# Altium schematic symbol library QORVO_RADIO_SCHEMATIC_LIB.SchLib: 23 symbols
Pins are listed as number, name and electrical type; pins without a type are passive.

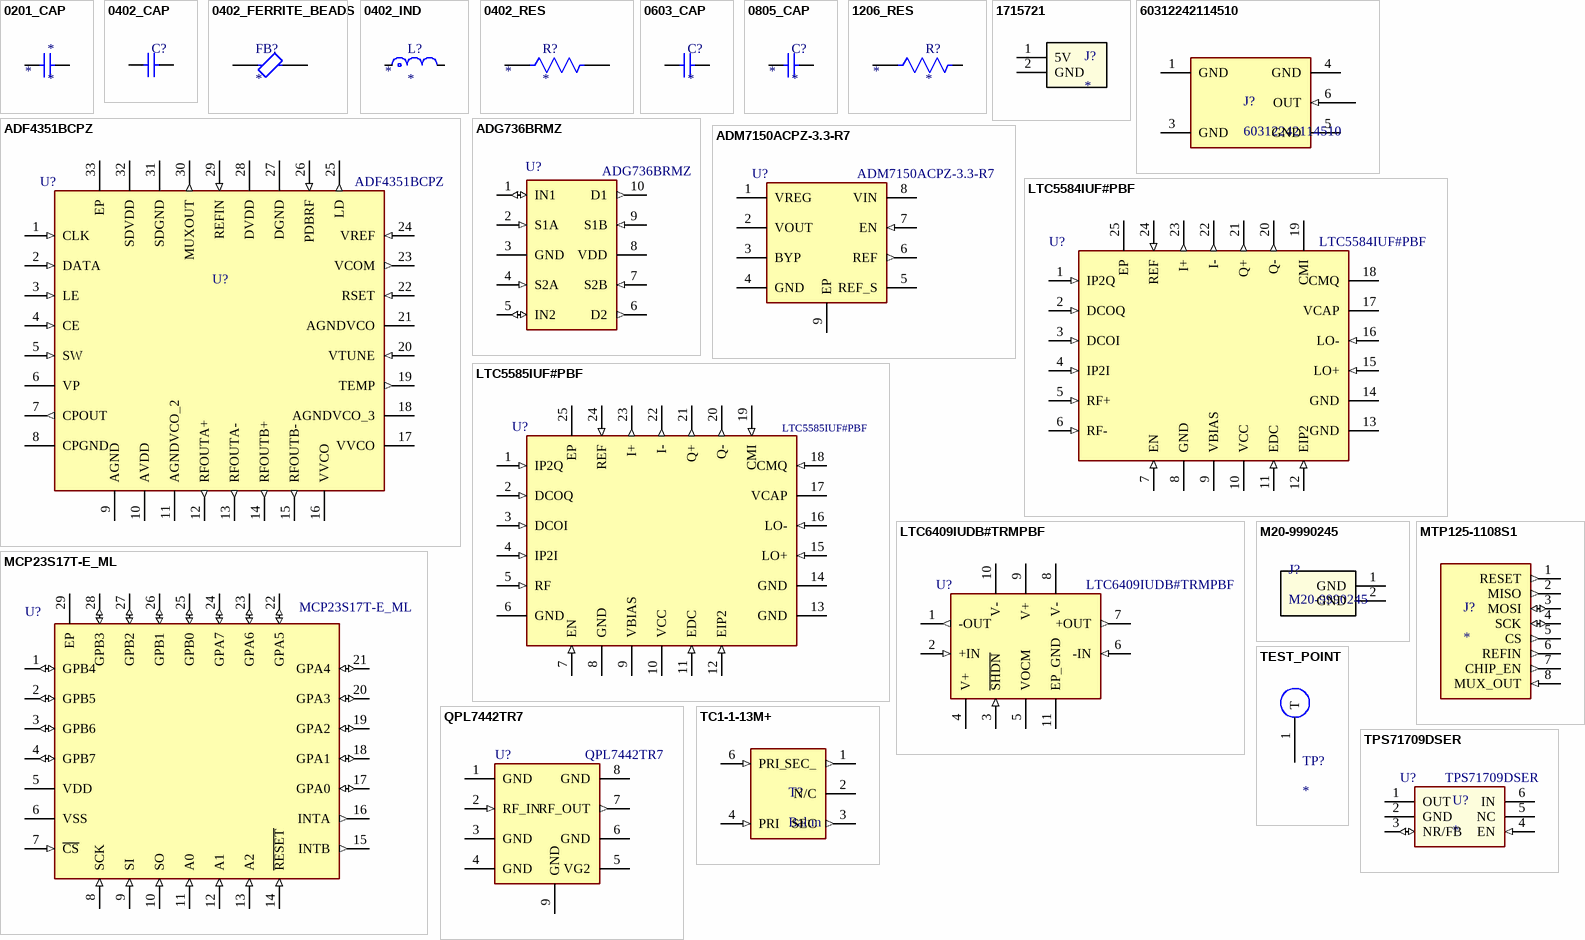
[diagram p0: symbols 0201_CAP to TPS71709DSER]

## 0201_CAP
designator *
CAPACITOR
footprint 0201_CAP
pins: 1, 2

## 0402_CAP
designator C?
CAPACITOR
footprint 0402 CAP_IND_RES
pins: 1, 2

## 0402_FERRITE_BEADS
designator FB?
FERRITE BEADS
footprint 0402 CAP_IND_RES
pins: 1, 2

## 0402_IND
designator L?
INDUCTOR
footprint 0402 CAP_IND_RES
pins: 1, 2

## 0402_RES
designator R?
RESISTOR
footprint 0402 CAP_IND_RES
pins: 1, 2

## 0603_CAP
designator C?
CAPACITOR
footprint 0603_CAP
pins: 1, 2

## 0805_CAP
designator C?
CAPACITOR
footprint 0805_CAP
pins: 1, 2

## 1206_RES
designator R?
RESISTOR
footprint 1206_RES
pins: 1, 2

## 1715721
designator J?
1x2P 17.5A 250V Green 14~30 Direct Insert 5.08mm 1 2 Plugin,P=5.08mm Screw Terminal Blocks ROHS; Mfr_Name: Phoenix Contact
footprint 1715721 (PS CONNECTOR)
pins: 1 5V (power), 2 GND (power)

## 60312242114510
designator J?
1 SMA Board Edge 18GHz 50Ω -  RF Connectors / Coaxial Connectors ROHS
footprint 60312242114510 (FEMALE SMA - EDGE MOUNT)
pins: 1 GND (power), 3 GND (power), 4 GND (power), 5 GND (power), 6 OUT (in)

## ADF4351BCPZ
designator U?  (value not drawn)
4.4GHz LFCSP-32(5x5) Clock Generators, PLLs, Frequency Synthesizers ROHS; Manufacturer_Name: Analog Devices; Manufacturer_Part_Number: ADF4351BCPZ
footprint ADF4351BCPZ (WIDEBAND SYNTHESIZER)
pins: 1 CLK (in), 2 DATA (in), 3 LE (in), 4 CE (in), 5 SW (in), 6 VP (power), 7 CPOUT (out), 8 CPGND (power), 9 AGND (power), 10 AVDD (power), 11 AGNDVCO_2 (power), 12 RFOUTA+ (out), 13 RFOUTA- (out), 14 RFOUTB+ (out), 15 RFOUTB- (out), 16 VVCO (power), 17 VVCO (power), 18 AGNDVCO_3 (power), 19 TEMP (out), 20 VTUNE (in), 21 AGNDVCO (power), 22 RSET (in), 23 VCOM (out), 24 VREF (in), 25 LD (out), 26 PDBRF (in), 27 DGND (power), 28 DVDD (power), 29 REFIN (in), 30 MUXOUT (out), 31 SDGND (power), 32 SDVDD (power), 33 EP (power)

## ADG736BRMZ
designator U?
2 4Ω SPDT(SPDT) MSOP-10  Analog Switches, Multiplexers ROHS; Manufacturer_Name: Analog Devices
footprint ADG736BRMZ
pins: 1 IN1 (io), 2 S1A (in), 3 GND (power), 4 S2A (in), 5 IN2 (io), 6 D2 (out), 7 S2B (in), 8 VDD (power), 9 S1B (in), 10 D1 (out)

## ADM7150ACPZ-3.3-R7
designator U?
800mA 68dB@(1MHz) Fixed 3.3V Positive electrode 16V LFCSP-8-EP(3x3) Voltage Regulators - Linear, Low Drop Out (LDO) Regulators ROHS; Manufacturer_Name: Analog Devices
footprint ADM7150ACPZ-3.3-R7 (3.3V REG)
pins: 1 VREG (power), 2 VOUT (power), 3 BYP, 4 GND (power), 5 REF_S, 6 REF (out), 7 EN (in), 8 VIN (power), 9 EP (power)

## LTC5584IUF#PBF
designator U?
30MHz~1.4GHz 9.9dB 5.4dB QFN-24-EP(4x4) RF Modulators and Demodulators ROHS; Manufacturer_Name: Analog Devices
footprint LTC5584/LTC5585 (MIXERS / LTC5585IUF#PBF / LTC5584IUF#PBF)
pins: 1 IP2Q (in), 2 DCOQ (in), 3 DCOI (in), 4 IP2I (in), 5 RF+ (in), 6 RF- (in), 7 EN (in), 8 GND (power), 9 VBIAS (power), 10 VCC (power), 11 EDC (in), 12 EIP2 (in), 13 GND (power), 14 GND (power), 15 LO+ (in), 16 LO- (in), 17 VCAP (power), 18 CMQ (power), 19 CMI (power), 20 Q- (out), 21 Q+ (out), 22 I- (out), 23 I+ (out), 24 REF (in), 25 EP (power)

## LTC5585IUF#PBF
designator U?
400MHz~4GHz 12.7dB 2.4dB QFN-24-EP(4x4)  RF Modulators and Demodulators ROHS; Manufacturer_Name: Analog Devices
footprint LTC5584/LTC5585 (MIXERS / LTC5585IUF#PBF / LTC5584IUF#PBF)
pins: 1 IP2Q (in), 2 DCOQ (in), 3 DCOI (in), 4 IP2I (in), 5 RF (in), 6 GND (power), 7 EN (in), 8 GND (power), 9 VBIAS (power), 10 VCC (power), 11 EDC (in), 12 EIP2 (in), 13 GND (power), 14 GND (power), 15 LO+ (in), 16 LO- (in), 17 VCAP (power), 18 CMQ (in), 19 CMI (in), 20 Q- (out), 21 Q+ (out), 22 I- (out), 23 I+ (out), 24 REF (in), 25 EP (power)

## LTC6409IUDB#TRMPBF
designator U?
QFN-10(2x3)  Differential Amplifiers ROHS; Manufacturer_Name: Analog Devices
footprint LTC6409IUDB#TRMPBF (DIFFERENTAL OP-AMP)
pins: 1 -OUT (out), 2 +IN (in), 3 ~{SHDN} (in), 4 V+ (power), 5 VOCM (power), 6 -IN (in), 7 +OUT (out), 8 V- (power), 9 V+ (power), 10 V- (power), 11 EP_GND (power)

## M20-9990245
designator J?
2 PIN HEADER FOR GND; Mfr_Name: Harwin
footprint GND_TEST (TEST POINT FOR GND HEADER)
pins: 1 GND (power), 2 GND (power)

## MCP23S17T-E_ML
designator U?
10MHz SPI QFN-28-EP(6x6) I/O Expanders ROHS; Manufacturer_Name: Microchip; Manufacturer_Part_Number: MCP23S17T-E/ML
footprint MCP23S17T-E_ML (I/O EXPANDER)
pins: 1 GPB4 (io), 2 GPB5 (io), 3 GPB6 (io), 4 GPB7 (io), 5 VDD (power), 6 VSS (power), 7 ~{CS} (in), 8 SCK (in), 9 SI (in), 10 SO (in), 11 A0 (in), 12 A1 (in), 13 A2 (in), 14 ~{RESET} (in), 15 INTB (out), 16 INTA (out), 17 GPA0 (io), 18 GPA1 (io), 19 GPA2 (io), 20 GPA3 (io), 21 GPA4 (io), 22 GPA5 (io), 23 GPA6 (io), 24 GPA7 (io), 25 GPB0 (io), 26 GPB1 (io), 27 GPB2 (io), 28 GPB3 (io), 29 EP

## MTP125-1108S1
designator J?
Direct Insert Policy 2.5mm 8P 6mm -40℃~+105℃ 3mm 2.54mm Single Row Black Brass 1x8P Plugin,P=2.54mm Pin Headers ROHS; MP: M20-9990645
footprint M20-9990845 (HEADER FOR I/O CONTROL - 8 PIN)
pins: 1 RESET (out), 2 MISO (out), 3 MOSI (io), 4 SCK (io), 5 CS (out), 6 REFIN (out), 7 CHIP_EN (out), 8 MUX_OUT (in)

## QPL7442TR7
designator U?
Qorvo QPL7442TR7
footprint QPL7442TR7 (LNA)
pins: 1 GND (power), 2 RF_IN (in), 3 GND (power), 4 GND (power), 5 VG2, 6 GND (power), 7 RF_OUT (out), 8 GND (power), 9 GND (power)

## TC1-1-13M+
designator T?, comment Balun
SMD,3.8x3.8mm RF Misc ICs and Modules ROHS
footprint TC1-1-13M+ (1:1 BALUN,)
pins: 1 SEC_ (out), 2 N/C, 3 SEC (out), 4 PRI (in), 6 PRI_ (in)

## TEST_POINT
designator TP?  (no BOM)
TEST POINT
footprint TEST POINT
pins: 1 T

## TPS71709DSER
designator U?
70dB@(100Hz) 150mA Fixed 900mV Positive electrode 6.5V WSON-6(1.5x1.5)  Voltage Regulators - Linear, Low Drop Out (LDO) Regulators ROHS; Mfr_Name: Texas Instruments; Manufacturer_part_number: TPS71709DSER
footprint TPS71709DSER (0.9V REG)
pins: 1 OUT (power), 2 GND (power), 3 NR/FB (io), 4 EN (in), 5 NC, 6 IN (power)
